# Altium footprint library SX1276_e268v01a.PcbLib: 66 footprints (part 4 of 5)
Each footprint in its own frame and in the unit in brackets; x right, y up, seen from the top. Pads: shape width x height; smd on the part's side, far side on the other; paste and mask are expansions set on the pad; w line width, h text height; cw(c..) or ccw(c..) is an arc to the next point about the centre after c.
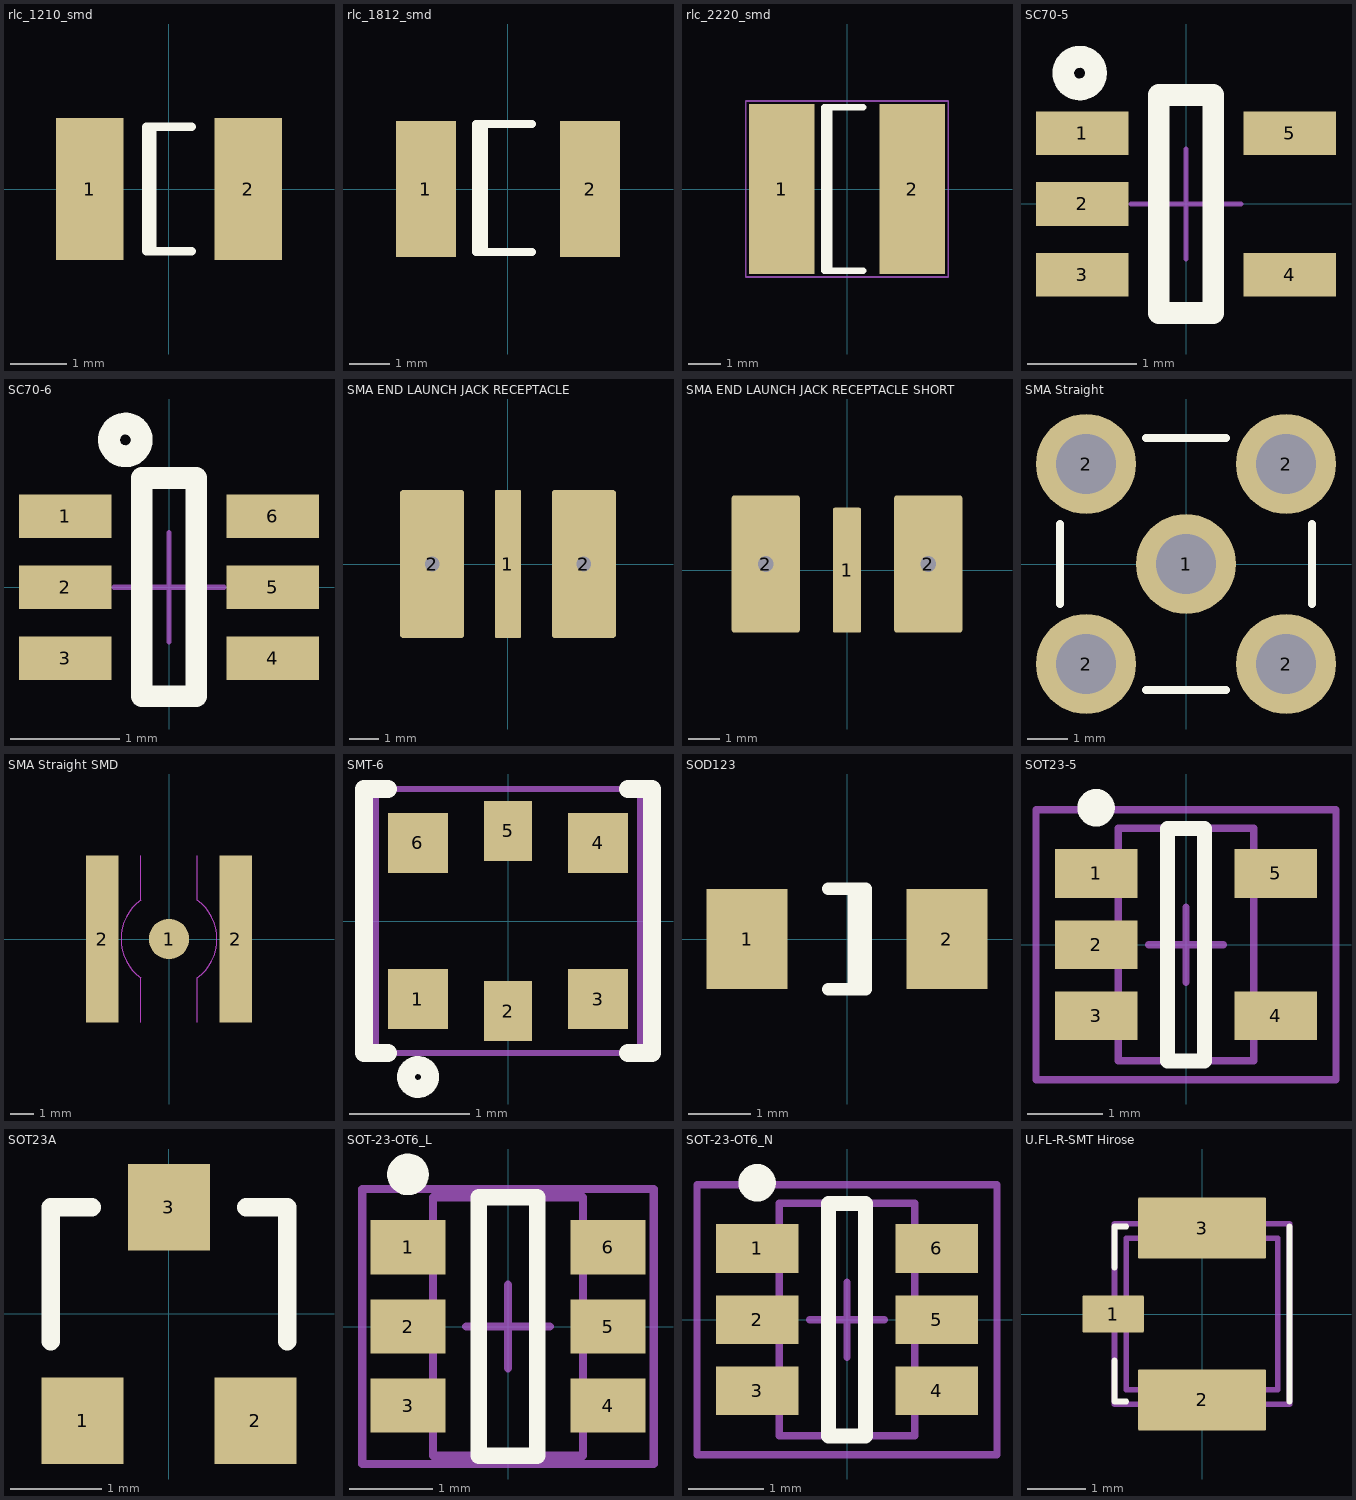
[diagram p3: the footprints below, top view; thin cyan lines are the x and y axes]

## rlc_1210_smd [mm] "Chip SMD component 1210; Body 3.2 x 2.5 mm (LxW typ)"
height 2
pads (2):
  rect 1.2x2.5 smd mask+0.05: 1(-1.4,0) 2(1.4,0)
Top Overlay:
  lines w0.15: -0.3,-1.1 -0.3,1.1 ; 0.4,-1.1 -0.4,-1.1 -0.4,1.1 0.4,1.1

## rlc_1812_smd [mm] "Chip SMD component 1812; Body 4.5 x 3.2 mm (LxW typ)"
height 2.5
pads (2):
  rect 1.5x3.4 smd mask+0.05: 1(-2.05,0) 2(2.05,0)
Top Overlay:
  lines w0.2: -0.606,-1.579 -0.606,1.621 ; 0.604,-1.579 -0.796,-1.579 -0.796,1.621 0.604,1.621

## rlc_2220_smd [mm] "Chip SMD component ; Body 5.7 x 5.0 mm (LxW typ)"
height 5
pads (2):
  rect 2x5.2 smd mask+0.05: 1(-2,0) 2(2,0)
Top Overlay:
  lines w0.2: -0.55,-2.5 -0.55,2.5 ; 0.5,-2.5 -0.7,-2.5 -0.7,2.5 0.5,2.5
Mechanical 15:
  lines w0.05: -3.1,-2.7 3.1,-2.7 3.1,2.7 -3.1,2.7 -3.1,-2.7

## SC70-5 [mm] "SC70 5-Leads, Body 2.0x1.25mm, Pitch 0.65mm"
height 1.45
pads (5):
  rect 0.85x0.4 smd mask+0.05: 1(-0.95,0.65) 2(-0.95,0) 3(-0.95,-0.65) 4(0.95,-0.65) 5(0.95,0.65)
Top Overlay:
  circle w0.2: c-0.975,1.2 r0.15
  lines w0.2: -0.25,-1 0.25,-1 0.25,1 -0.25,1 -0.25,-1
Mechanical 15:
  lines w0.05: -0.5,0 0.5,0 ; 0,-0.5 0,0.5
3D body: height 1.45, standoff 0, extent -0.625,-1 0.625,1

## SC70-6 [mm] "SC70 6-Leads, Body 2.0x1.25mm, Pitch 0.65mm"
height 1.45
pads (6):
  rect 0.85x0.4 smd mask+0.05: 1(-0.95,0.65) 2(-0.95,0) 3(-0.95,-0.65) 4(0.95,-0.65) 5(0.95,0) 6(0.95,0.65)
Top Overlay:
  circle w0.2: c-0.4,1.35 r0.15
  lines w0.2: -0.25,-1 0.25,-1 0.25,1 -0.25,1 -0.25,-1
Mechanical 15:
  lines w0.05: -0.5,0 0.5,0 ; 0,-0.5 0,0.5
3D body: height 1.45, standoff 0, extent -0.625,-1 0.625,1

## SMA END LAUNCH JACK RECEPTACLE [mm] "SMA Connector - End Launch Jack Receptacle"
height 8
pads (3):
  rrect10% 0.9x5.08 smd paste+0 mask+0.05: 1(0,0)
  rrect10% 2.2x5.08 hole 0.5 mask+0.05: 2(-2.6,0) 2(2.6,0)

## SMA END LAUNCH JACK RECEPTACLE SHORT [mm] "SMA Connector - End Launch Jack Receptacle - Short"
height 8
pads (3):
  rrect10% 0.9x4 smd paste+0 mask+0.05: 1(0,0)
  rrect10% 2.2x4.4 hole 0.5 mask+0.05: 2(-2.6,0.2) 2(2.6,0.2)

## SMA Straight [mm] "SMA Connector; Straight"
height 10
pads (5):
  round 2.5 hole 1.5 paste+0 mask+0.1: 1(0,0) 2(-2.5,-2.5) 2(-2.5,2.5) 2(2.5,-2.5) 2(2.5,2.5)
Top Overlay:
  lines w0.2: -3.15,-1 -3.15,1 ; -1,-3.15 1,-3.15 ; -1,3.15 1,3.15 ; 3.15,-1 3.15,1
Mechanical 1:
  circle w0.025: c0,0 r0.2

## SMA Straight SMD [mm] "SMA Connector; Straight; SMD"
height 10
pads (3):
  round 1.73 smd paste+0 mask+0.05: 1(0,0)
  rect 1.4x7.12 smd paste+0 mask+0.05: 2(-2.85,0) 2(2.85,0)
Top Paste:
  region: -1.24,3.56 -1.24,1.71 -2.24,1.71 -2.24,3.56
  region: 2.25,3.56 2.25,1.71 1.25,1.71 1.25,3.56
  region: 2.25,-1.7 2.25,-3.55 1.25,-3.55 1.25,-1.7
  region: -1.25,-1.7 -1.25,-3.55 -2.25,-3.55 -2.25,-1.7
Top Solder:
  region: -1.21,-4 -3.8,-4 -3.8,-3.55 -1.21,-3.55
  region: -3.5,4 -3.9,4 -3.9,-4 -3.5,-4
  region: -3.8,3.55 -3.8,4 -1.2,4 -1.2,3.55
  region: -2.13,-3.61 -1.21,-3.61 -1.21,-1.66 -2.13,-0.8
  region: -2.12,3.61 -1.2,3.61 -1.2,1.66 -2.12,0.8
  region: 2.13,3.61 1.21,3.61 1.21,1.66 2.13,0.8
  region: 2.13,-3.61 1.21,-3.61 1.21,-1.66 2.13,-0.8
  region: 3.8,-4 1.21,-4 1.21,-3.55 3.8,-3.55
  region: 3.9,4 3.5,4 3.5,-4 3.9,-4
  region: 1.21,3.55 1.21,4 3.8,4 3.8,3.55
Mechanical 12 keep-out:
  lines w0.05: -1.212,-1.653 cw(c0,0) -1.208,1.657 ; -1.21,-3.565 -1.21,-1.66 ; -1.2,1.66 -1.2,3.565 ; 1.208,-3.558 1.208,-1.657 ccw(c0,0) 1.212,1.653 ; 1.21,1.66 1.21,3.56

## SMT-6 [mm] "SMT-6 Package"
height 1.25
pads (6):
  rect 0.5x0.5 smd mask+0.05: 1(-0.75,-0.65) 3(0.75,-0.65) 4(0.75,0.65) 6(-0.75,0.65)
  rect 0.4x0.5 smd mask+0.05: 2(0,-0.75) 5(0,0.75)
Top Overlay:
  circle w0.15: c-0.75,-1.3 r0.1
  lines w0.15: -1,-1.1 -1.2,-1.1 -1.2,1.1 -1,1.1 ; 1,-1.1 1.2,-1.1 1.2,1.1 1,1.1
Mechanical 15:
  lines w0.05: -1.1,-1.1 -1.1,1.1 1.1,1.1 1.1,-1.1 -1.1,-1.1
3D body: height 1, standoff 0, extent -0.85,-0.85 0.85,0.85

## SOD123 [mm] "SOD123; Chip Diode; Body  2.7 x 1.6 mm (LxW typ)"
height 1.35
pads (2):
  rect 1.3x1.6 smd mask+0.05: 1(-1.6,0) 2(1.6,0)
Top Overlay:
  lines w0.2: -0.3,-0.8 0.3,-0.8 0.3,0.8 -0.3,0.8 ; 0.11,-0.8 0.11,0.8

## SOT23-5 [mm] "SOT23, 5-Leads, Body 2.9x1.6mm, Pitch 0.95mm, Lead Span 2.8mm, IPC Medium Density"
height 1.45
pads (5):
  rect 1.1x0.65 smd mask+0.05: 1(-1.2,0.95) 2(-1.2,0) 3(-1.2,-0.95) 4(1.2,-0.95) 5(1.2,0.95)
Top Overlay:
  circle w0.25: c-1.2,1.825 r0.125
  lines w0.2: -0.25,-1.55 -0.25,1.55 0.25,1.55 0.25,-1.55 -0.25,-1.55
Mechanical 13:
  lines w0.1: -0.9,-1.55 0.9,-1.55 0.9,1.55 -0.9,1.55 -0.9,-1.55
Mechanical 15:
  lines w0.1: -0.5,0 0.5,0 ; 0,-0.5 0,0.5 ; -2,-1.8 2,-1.8 2,1.8 -2,1.8 -2,-1.8
3D body: height 1.45, standoff 0, extent -0.9,-1.55 0.9,1.55

## SOT23A [mm] "SOT-23; 3 Leads; Body 3.0 x 2.5 mm, inc. leads (LxW max)"
height 1.2
pads (3):
  rect 0.9x0.95 smd: 1(-0.95,-1.175) 2(0.95,-1.175) 3(0,1.175)
Top Overlay:
  lines w0.2: -1.3,-0.3 -1.3,1.175 -0.85,1.175 ; 0.85,1.175 1.3,1.175 1.3,-0.3

## SOT-23-OT6_L [mm] "SOT23, 6-Leads, Body 2.9x1.6mm, Pitch 0.95mm, Lead Span 2.7mm, IPC High Density"
height 1.45
pads (6):
  rect 0.9x0.65 smd: 1(-1.2,0.95) 2(-1.2,0) 3(-1.2,-0.95) 4(1.2,-0.95) 5(1.2,0) 6(1.2,0.95)
Top Overlay:
  circle w0.25: c-1.2,1.825 r0.125
  lines w0.2: -0.35,-1.55 0.35,-1.55 0.35,1.55 -0.35,1.55 -0.35,-1.55
Mechanical 13:
  lines w0.1: -0.9,-1.55 -0.9,1.55 0.9,1.55 0.9,-1.55 -0.9,-1.55
Mechanical 15:
  lines w0.1: -0.5,0 0.5,0 ; 0,-0.5 0,0.5 ; -1.75,-1.65 -1.75,1.65 1.75,1.65 1.75,-1.65 -1.75,-1.65
3D body: height 1.45, standoff 0, extent -0.9,-1.55 0.9,1.55

## SOT-23-OT6_N [mm] "SOT23, 6-Leads, Body 2.9x1.6mm, Pitch 0.95mm, Lead Span 2.7mm, IPC Medium Density"
height 1.45
pads (6):
  rect 1.1x0.65 smd: 1(-1.2,0.95) 2(-1.2,0) 3(-1.2,-0.95) 4(1.2,-0.95) 5(1.2,0) 6(1.2,0.95)
Top Overlay:
  circle w0.25: c-1.2,1.825 r0.125
  lines w0.2: -0.25,-1.55 -0.25,1.55 0.25,1.55 0.25,-1.55 -0.25,-1.55
Mechanical 13:
  lines w0.1: -0.9,-1.55 0.9,-1.55 0.9,1.55 -0.9,1.55 -0.9,-1.55
Mechanical 15:
  lines w0.1: -0.5,0 0.5,0 ; 0,-0.5 0,0.5 ; -2,-1.8 2,-1.8 2,1.8 -2,1.8 -2,-1.8
3D body: height 1.45, standoff 0, extent -0.9,-1.55 0.9,1.55

## U.FL-R-SMT Hirose [mm] "Hirose U.FL RF receptacle - U.FL-R-SMT"
height 1.2
pads (3):
  rrect5% 1.05x0.635 smd: 1(-1.525,0)
  rrect5% 2.2x1.05 smd: 2(0,-1.475) 3(0,1.475)
Top Overlay:
  lines w0.1: -1.5,-0.8 -1.5,-1.5 -1.3,-1.5 ; -1.5,0.8 -1.5,1.5 -1.3,1.5 ; 1.5,-1.5 1.5,1.5
Mechanical 13:
  lines w0.1: -1.5,-1.55 1.5,-1.55 1.5,1.55 -1.5,1.55 -1.5,-1.55
Mechanical 15:
  lines w0.1: -1.3,-1.3 1.3,-1.3 1.3,1.3 -1.3,1.3 -1.3,-1.3
3D body: height 16, standoff 1.3, extent -1.5,-1.5 1.5,1.5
